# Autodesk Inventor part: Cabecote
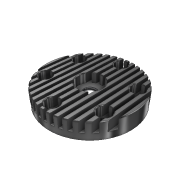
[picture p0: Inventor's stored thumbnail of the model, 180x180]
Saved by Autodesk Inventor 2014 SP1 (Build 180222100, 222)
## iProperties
Created: 2013-12
Part Number: Cabecote
Material: Generic
Document SubType Name: Modeling
Designer: User
Density: 1 g/cm^3
Appearance: Chrome - Polished Black
Author: User
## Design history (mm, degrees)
sketch "Sketch1"
  geometry: C1 r 14.5 at (0, 0); 1 further point
  constraints: 1 centre point, 1 coincident
  dimensions: "d0" = 29 diameter of C1
extrude "Extrusion1" new body sketch "Sketch1" distance "d1" = 5; taper "d2" = 0 deg
sketch "Sketch2"
  geometry: C1 r 14.5 at (0, 0) reference; 1 further point
  dimensions: "d3" = 11.5 distance of C1.centre point (0, 11.5)
hole "Hole1" sketch "Sketch2" at (0, 11.5) diameter "d4" = 2.5; stored, may be unused: countersink angle "d8" = 90 deg, drill point angle "d10" = 118 deg; dims "d5" = 6, "d6" = 4, "d7" = 3, "d9" = 8
pattern_circular "Circular Pattern1" dims angle "d12" = 360 deg
sketch "Sketch3"
  geometry: C1 r 14.5 at (0, 0) reference; C2 r 4 at (0, 0)
  constraints: 1 centre point, 1 coincident
  dimensions: "d14" = 8 diameter of C2
extrude "Extrusion2" cut sketch "Sketch3" distance "d15" = 3; taper "d16" = 0 deg
sketch "Sketch4"
  geometry: C1 r 14.5 at (0, 0) reference; C2 r 8 at (0, 0)
  constraints: 1 centre point, 1 coincident
  dimensions: "d17" = 16 diameter of C2
extrude "Extrusion3" cut sketch "Sketch4" distance "d18" = 1; taper "d19" = 0 deg
sketch "Sketch7"
  geometry: 1 further point
hole "Hole2" sketch "Sketch7" at (0, 0) diameter "d20" = 4.134; stored, may be unused: countersink angle "d24" = 90 deg, drill point angle "d26" = 118 deg; dims "d21" = 6, "d22" = 4, "d23" = 3, "d25" = 8
chamfer "Chamfer1" distance "d27" = 0.2; stored, may be unused: second distance "d28" = 2, angle "d29" = 45 deg
sketch "Sketch8"
  geometry: L1 (-1.5, -17.267)-(-0.5, -17.267); L2 (-0.5, -17.267)-(-0.5, 16.783); L3 (-0.5, 16.783)-(-1.5, 16.783); L4 (-1.5, 16.783)-(-1.5, -17.267); L5 (-1.5, -17.267)-(-0.5, 16.783); L6 (-0.5, -17.267)-(-1.5, 16.783); L7 (-3.5, -17.267)-(-2.5, -17.267); L8 (-2.5, -17.267)-(-2.5, 16.783); L9 (-2.5, 16.783)-(-3.5, 16.783); L10 (-3.5, 16.783)-(-3.5, -17.267); L11 (-3.5, -17.267)-(-2.5, 16.783); L12 (-2.5, -17.267)-(-3.5, 16.783); L13 (-5.5, -17.267)-(-4.5, -17.267); L14 (-4.5, -17.267)-(-4.5, 16.783); L15 (-4.5, 16.783)-(-5.5, 16.783); L16 (-5.5, 16.783)-(-5.5, -17.267); L17 (-5.5, -17.267)-(-4.5, 16.783); L18 (-4.5, -17.267)-(-5.5, 16.783); L19 (-7.5, -17.267)-(-6.5, -17.267); L20 (-6.5, -17.267)-(-6.5, 16.783); L21 (-6.5, 16.783)-(-7.5, 16.783); L22 (-7.5, 16.783)-(-7.5, -17.267); L23 (-7.5, -17.267)-(-6.5, 16.783); L24 (-6.5, -17.267)-(-7.5, 16.783); L25 (-9.5, -17.267)-(-8.5, -17.267); L26 (-8.5, -17.267)-(-8.5, 16.783); L27 (-8.5, 16.783)-(-9.5, 16.783); L28 (-9.5, 16.783)-(-9.5, -17.267); L29 (-9.5, -17.267)-(-8.5, 16.783); L30 (-8.5, -17.267)-(-9.5, 16.783); L31 (-11.5, -17.267)-(-10.5, -17.267); L32 (-10.5, -17.267)-(-10.5, 16.783); L33 (-10.5, 16.783)-(-11.5, 16.783); L34 (-11.5, 16.783)-(-11.5, -17.267); L35 (-11.5, -17.267)-(-10.5, 16.783); L36 (-10.5, -17.267)-(-11.5, 16.783); L37 (-13.5, -17.267)-(-12.5, -17.267); L38 (-12.5, -17.267)-(-12.5, 16.783); L39 (-12.5, 16.783)-(-13.5, 16.783); L40 (-13.5, 16.783)-(-13.5, -17.267); L41 (-13.5, -17.267)-(-12.5, 16.783); L42 (-12.5, -17.267)-(-13.5, 16.783); L43 (0.5, -17.267)-(1.5, -17.267); L44 (1.5, -17.267)-(1.5, 16.783); L45 (1.5, 16.783)-(0.5, 16.783); L46 (0.5, 16.783)-(0.5, -17.267); L47 (0.5, -17.267)-(1.5, 16.783); L48 (1.5, -17.267)-(0.5, 16.783); L49 (-1.5, -17.267)-(-0.5, -17.267); L50 (-0.5, -17.267)-(-0.5, 16.783); L51 (-0.5, 16.783)-(-1.5, 16.783); L52 (-1.5, 16.783)-(-1.5, -17.267); L53 (-1.5, -17.267)-(-0.5, 16.783); L54 (-0.5, -17.267)-(-1.5, 16.783); L55 (-3.5, -17.267)-(-2.5, -17.267); L56 (-2.5, -17.267)-(-2.5, 16.783); L57 (-2.5, 16.783)-(-3.5, 16.783); L58 (-3.5, 16.783)-(-3.5, -17.267); L59 (-3.5, -17.267)-(-2.5, 16.783); L60 (-2.5, -17.267)-(-3.5, 16.783); L61 (-5.5, -17.267)-(-4.5, -17.267); L62 (-4.5, -17.267)-(-4.5, 16.783); L63 (-4.5, 16.783)-(-5.5, 16.783); L64 (-5.5, 16.783)-(-5.5, -17.267)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; C1 r 2.067 at (0, 0) reference; 56 further points
  constraints: 672 end point, 112 midpoint, 3 horizontal, 2 collinear, 2 parallel, 1 perpendicular, 603 other
  dimensions: "d30" = 0.5 distance from line of C1.centre L2; "d31" = 1 distance of L2.end L3.end; "d34" = 2 distance of L1.start L7.start; "d37" = 2 distance of L1.start L43.start
extrude "Extrusion4" cut sketch "Sketch8" distance "d40" = 3; taper "d41" = 0 deg
body "Solid1"
